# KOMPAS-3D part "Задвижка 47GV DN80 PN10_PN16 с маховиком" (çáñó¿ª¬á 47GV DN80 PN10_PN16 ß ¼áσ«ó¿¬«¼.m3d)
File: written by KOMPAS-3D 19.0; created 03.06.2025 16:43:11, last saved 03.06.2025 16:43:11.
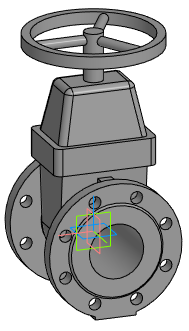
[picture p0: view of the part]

Document properties: Автор: Евгений; Полное имя файла: E:\Dendor Работа Сачек\3D для проекитирвщиков\2.1 Тип 47GV, 47GV.Z Задвижка клиновая фланцевая с обрезиненным клином\stp_Тип 47GV. Задвижка DN40-DN350 с маховиком\Задвижка 47GV DN80 PN10_PN16 с маховиком.m3d

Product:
- Part/product: Задвижка 47GV DN80 PN10_PN16 с маховиком

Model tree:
1. Операция без истории:1  (labels: Задвижка 47GV DN80 PN10_PN16 с маховиком)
